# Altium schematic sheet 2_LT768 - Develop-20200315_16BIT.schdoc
size 655 x 261 mm
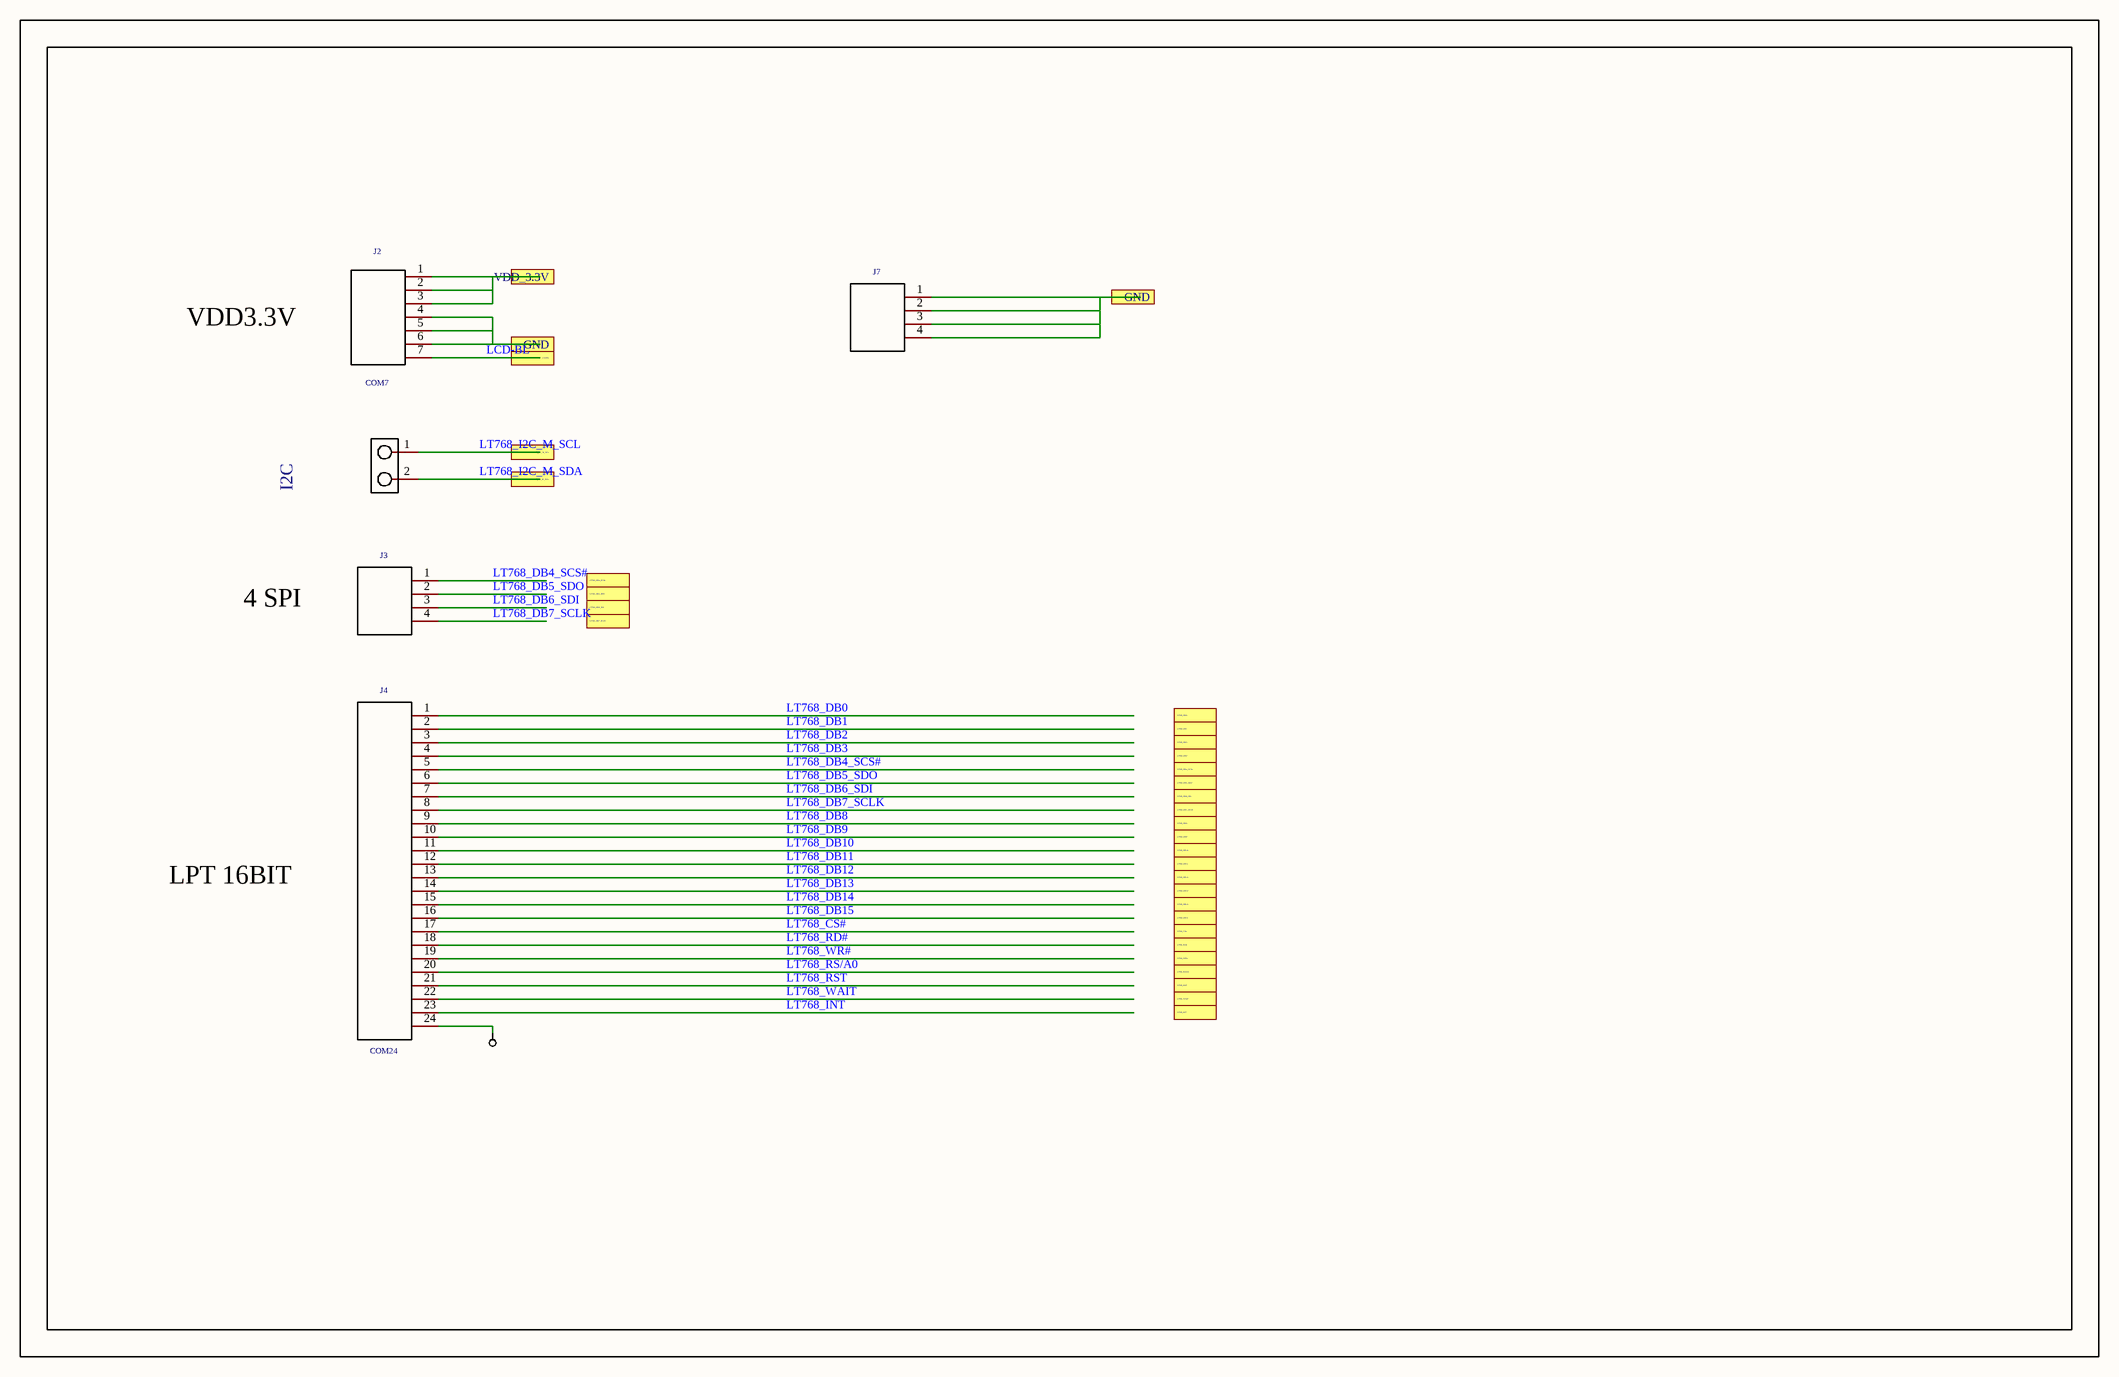
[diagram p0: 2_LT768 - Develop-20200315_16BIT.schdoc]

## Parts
I2C  COM2  (value not drawn)
J2  COM7  [COM7]
J3  COM4  (value not drawn)
J4  COM24
J7  COM4  (value not drawn)

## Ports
GND (in), LCD-BL (in), LT768_CS# (out), LT768_DB0 (out), LT768_DB1 (out), LT768_DB2 (out), LT768_DB3 (out), LT768_DB4_SCS# (out), LT768_DB5_SDO (out), LT768_DB6_SDI (out), LT768_DB7_SCLK (out), LT768_DB8 (out), LT768_DB9 (out), LT768_DB10 (out), LT768_DB11 (out), LT768_DB12 (out), LT768_DB13 (out), LT768_DB14 (out), LT768_DB15 (out), LT768_I2C_M_SCL (in), LT768_I2C_M_SDA (in), LT768_INT (out), LT768_RD# (out), LT768_RS/A0 (out), LT768_RST (out), LT768_WAIT (out), LT768_WR# (out), VDD_3.3V (in)

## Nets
GND: J4.24
GND: J2.4 J2.5 J2.6 J7.1 J7.2 J7.3 J7.4 ; port GND  [a separate net that carries the same name]
LCD-BL: J2.7 ; port LCD-BL
LT768_CS#: J4.17
LT768_DB0: J4.1
LT768_DB1: J4.2
LT768_DB2: J4.3
LT768_DB3: J4.4
LT768_DB4_SCS#: J3.1 J4.5
LT768_DB5_SDO: J3.2 J4.6
LT768_DB6_SDI: J3.3 J4.7
LT768_DB7_SCLK: J3.4 J4.8
LT768_DB8: J4.9
LT768_DB9: J4.10
LT768_DB10: J4.11
LT768_DB11: J4.12
LT768_DB12: J4.13
LT768_DB13: J4.14
LT768_DB14: J4.15
LT768_DB15: J4.16
LT768_I2C_M_SCL: I2C.1 ; port LT768_I2C_M_SCL
LT768_I2C_M_SDA: I2C.2 ; port LT768_I2C_M_SDA
LT768_INT: J4.23
LT768_RD#: J4.18
LT768_RS/A0: J4.20
LT768_RST: J4.21
LT768_WAIT: J4.22
LT768_WR#: J4.19
VDD_3.3V: J2.1 J2.2 J2.3 ; port VDD_3.3V

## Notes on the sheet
- VDD3.3V
- 4 SPI
- LPT 16BIT

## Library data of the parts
I2C = COM2: Header; Symbol: CON2_PIN; Add into BOM: yes; PCB DECAL: JACK/2.54MM
J2 = COM7: Header; Add into BOM: yes
J3 J7 = COM4: Header; Add into BOM: yes; PCB DECAL: SIP-4P
J4 = COM24: Header; Add into BOM: yes; PCB DECAL: SIP-24P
